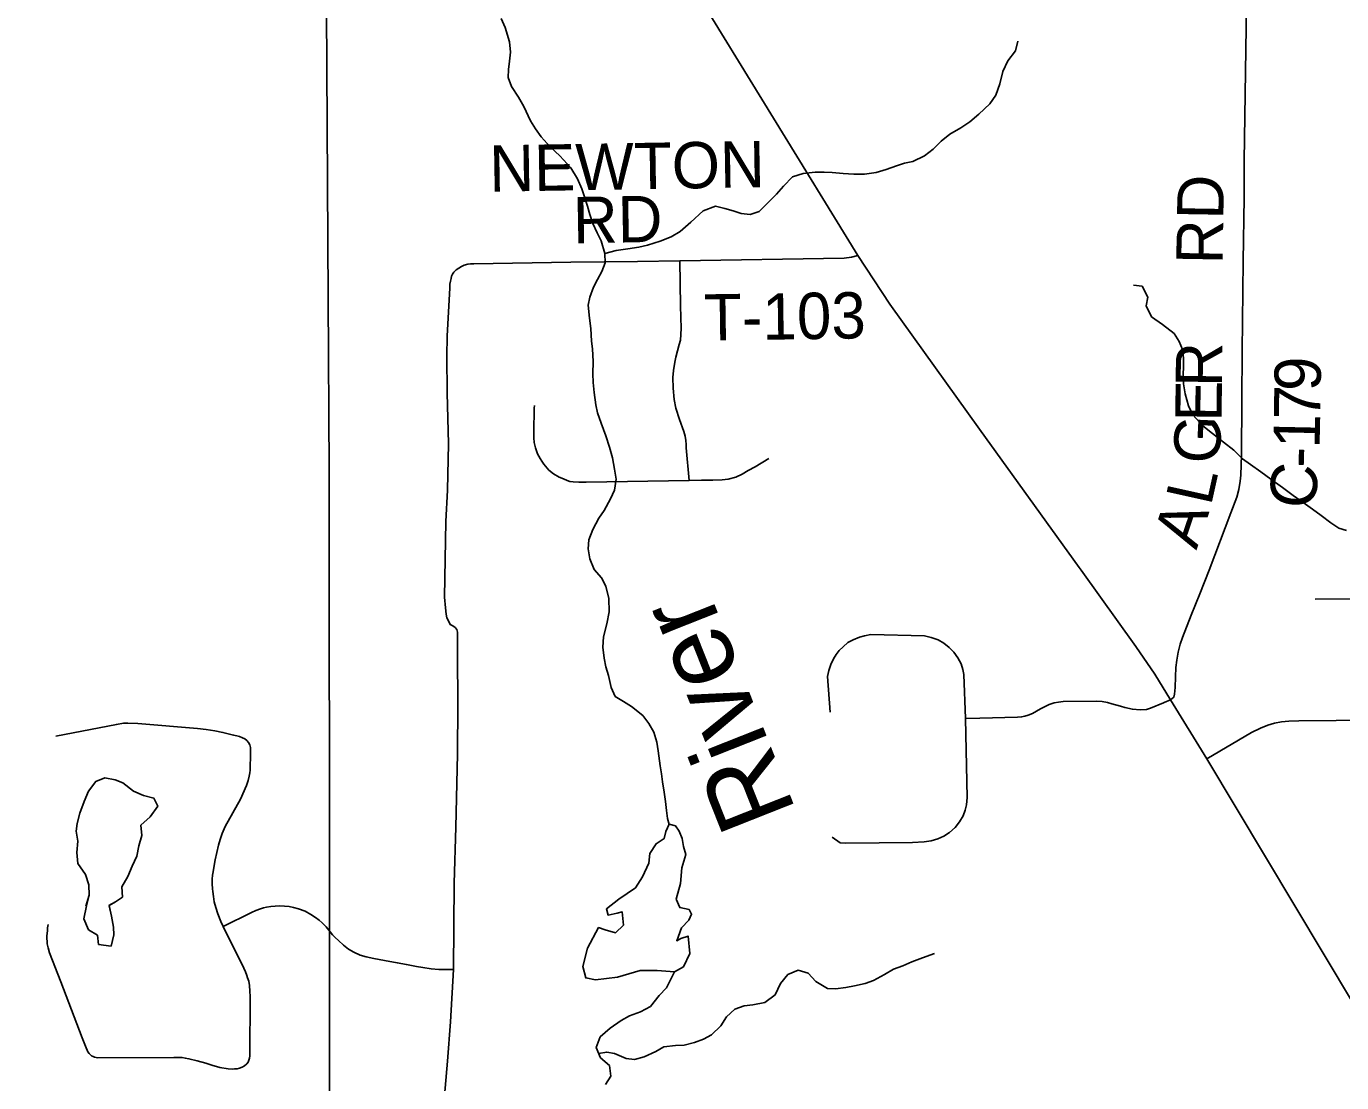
# Model space of a CAD drawing. Extents: x 0 to 34, y 0 to 22.
# Drawn here: x 2.919 to 4.531, y 18.93 to 20.225 of the extents above; entities that cross this region are included whole.
import ezdxf

# ---------------------------------------------------------------- set-up
doc = ezdxf.new("R2010")
doc.units = 0
for name, color, linetype in [('Default', 7, 'Continuous'), ('GM_X_City_Street', 7, 'Continuous'), ('GM_X_County_Road', 7, 'Continuous'), ('GM_X_County_Road_Text', 7, 'Continuous'), ('GM_X_Minor_Lake', 7, 'Continuous'), ('GM_X_Minor_River', 7, 'Continuous'), ('GM_X_Minor_River_Text', 7, 'Continuous'), ('GM_X_State_Route', 7, 'Continuous'), ('GM_X_Township_Road', 7, 'Continuous'), ('GM_X_Township_Road_Text', 7, 'Continuous'), ('SH_Cut_Line', 7, 'Continuous')]:
    doc.layers.add(name, color=color, linetype=linetype)

msp = doc.modelspace()

# ---------------------------------------------------------------- linework, layer by layer
at = {"layer": 'Default'}
msp.add_lwpolyline([(3.2826, 20.9), (2.1, 20.9), (2.1, 15.8248), (3.2829, 15.8433), (3.2832, 16.3898), (3.2835, 17.0107), (3.2837, 17.3796), (3.2907, 18.4315), (3.2904, 19.1173), (3.2901, 19.68), (3.2888, 19.8918), (3.2845, 20.5998), (3.2843, 20.6124)], close=True, dxfattribs=at)
msp.add_lwpolyline([(8.1749, 20.9), (3.2826, 20.9), (3.2843, 20.6124), (3.2845, 20.5998), (3.2888, 19.8918), (3.2901, 19.68), (3.2904, 19.1173), (3.2907, 18.4315), (3.2837, 17.3796), (3.2835, 17.0107), (3.2832, 16.3898), (3.2829, 15.8433), (3.425, 15.8449), (3.4609, 15.8448), (3.6703, 15.8472), (4.3446, 15.8524), (4.6273, 15.8569)], dxfattribs=at)
at = {"layer": 'GM_X_City_Street'}
for points in [[(4.3214, 19.3994), (4.3252, 19.4025), (4.3261, 19.4061), (4.3269, 19.4144), (4.3276, 19.4277), (4.3279, 19.4388), (4.329, 19.4479), (4.3308, 19.4577), (4.3332, 19.4676), (4.3361, 19.4757), (4.3468, 19.5031), (4.3573, 19.5295), (4.3685, 19.5583)], [(4.4986, 19.5226), (4.6144, 19.5236), (4.6796, 19.5238)], [(4.3659, 19.327), (4.4205, 19.3591), (4.4317, 19.3646), (4.4405, 19.3681), (4.4488, 19.3706), (4.4575, 19.3722), (4.4663, 19.3731), (4.4785, 19.3736), (4.6158, 19.3747)]]:
    msp.add_lwpolyline(points, dxfattribs=at)
at = {"layer": 'GM_X_County_Road'}
for points in [[(4.4118, 20.0552), (4.4118, 20.0602), (4.4144, 20.2509), (4.4155, 20.3706)], [(4.4116, 20.0148), (4.4117, 20.0189), (4.4118, 20.0552)], [(4.3685, 19.5583), (4.3953, 19.6286), (4.4026, 19.6479), (4.405, 19.6573), (4.4067, 19.6676), (4.4076, 19.6747), (4.4084, 19.6997), (4.4089, 19.7665), (4.4093, 19.8269), (4.4104, 19.9371), (4.4116, 20.0148)]]:
    msp.add_lwpolyline(points, dxfattribs=at)
at = {"layer": 'GM_X_Minor_Lake'}
for points in [[(3.0371, 19.2974), (3.0276, 19.3011), (3.015, 19.3036), (3.0037, 19.2992), (2.9951, 19.2873), (2.9896, 19.2747), (2.9841, 19.2605), (2.9809, 19.2479), (2.9799, 19.2384), (2.982, 19.2259), (2.9807, 19.2122), (2.9817, 19.1985), (2.9914, 19.185), (2.9954, 19.1725), (2.9957, 19.1599), (2.9923, 19.1466)], [(3.0371, 19.2974), (3.0276, 19.3011), (3.015, 19.3036), (3.0037, 19.2992), (2.9951, 19.2873), (2.9896, 19.2747), (2.9841, 19.2605), (2.9809, 19.2479), (2.9799, 19.2384), (2.982, 19.2259), (2.9807, 19.2122), (2.9817, 19.1985), (2.9914, 19.185), (2.9954, 19.1725), (2.9957, 19.1599), (2.9917, 19.1464)], [(3.0198, 19.147), (3.028, 19.1516), (3.0367, 19.1574), (3.0356, 19.1701), (3.043, 19.1827), (3.0485, 19.1954), (3.054, 19.2076), (3.0565, 19.2202), (3.0601, 19.2332), (3.0591, 19.2457), (3.0704, 19.2557), (3.0797, 19.2688), (3.075, 19.2786), (3.0624, 19.2819), (3.0502, 19.2874), (3.0371, 19.2974)], [(3.0201, 19.1472), (3.028, 19.1516), (3.0367, 19.1574), (3.0356, 19.1701), (3.043, 19.1827), (3.0485, 19.1954), (3.054, 19.2076), (3.0565, 19.2202), (3.0601, 19.2332), (3.0591, 19.2457), (3.0704, 19.2557), (3.0797, 19.2688), (3.075, 19.2786), (3.0624, 19.2819), (3.0502, 19.2874), (3.0371, 19.2974)], [(3.7153, 19.1551), (3.7207, 19.1741), (3.7224, 19.1935), (3.7272, 19.2098), (3.7245, 19.2197), (3.7225, 19.2292), (3.719, 19.2382), (3.7144, 19.245), (3.7068, 19.2469), (3.7027, 19.2381), (3.7005, 19.2293), (3.6907, 19.2228), (3.6829, 19.211), (3.6818, 19.1992), (3.674, 19.1824), (3.6654, 19.169), (3.6449, 19.1549)], [(2.9923, 19.1466), (2.989, 19.1308), (2.9951, 19.1175), (3.0061, 19.1106), (3.0071, 19.0993)], [(3.0071, 19.0992), (3.0061, 19.1106), (2.9951, 19.1175), (2.989, 19.1308), (2.9923, 19.1466)], [(3.0071, 19.0993), (3.0225, 19.0974), (3.0259, 19.111), (3.0255, 19.1206), (3.0232, 19.1339), (3.0201, 19.1472)], [(3.0201, 19.1468), (3.0232, 19.1339), (3.0255, 19.1206), (3.0259, 19.111), (3.0225, 19.0974), (3.0072, 19.0993)], [(3.6449, 19.1549), (3.6298, 19.143), (3.6318, 19.1354), (3.6428, 19.1378), (3.6492, 19.1394), (3.6509, 19.1231), (3.6411, 19.1138), (3.6282, 19.1175), (3.6202, 19.1201), (3.6067, 19.0949), (3.6009, 19.0724), (3.6044, 19.0584), (3.6166, 19.0562), (3.6435, 19.0591), (3.6711, 19.0674), (3.692, 19.0676), (3.7133, 19.0659), (3.7242, 19.0721), (3.732, 19.0885), (3.7299, 19.1097), (3.7209, 19.1066), (3.716, 19.1039), (3.7219, 19.1199), (3.7309, 19.1291), (3.7343, 19.1364), (3.7312, 19.1421), (3.7198, 19.1446), (3.7153, 19.1551)]]:
    msp.add_lwpolyline(points, dxfattribs=at)
at = {"layer": 'GM_X_Minor_River'}
for points in [[(3.5009, 20.2346), (3.5055, 20.2236), (3.511, 20.2062), (3.5122, 20.1933), (3.5108, 20.1823), (3.5097, 20.172), (3.5094, 20.1625), (3.5133, 20.1512), (3.5221, 20.1383), (3.5287, 20.127), (3.5368, 20.1092), (3.5429, 20.0994), (3.5498, 20.0896), (3.5609, 20.0775), (3.5727, 20.0662), (3.5861, 20.0516), (3.5942, 20.0383), (3.5996, 20.0258), (3.6031, 20.016), (3.6066, 20.0046), (3.6093, 19.9944), (3.6132, 19.9834), (3.6186, 19.9721), (3.6232, 19.9623), (3.6279, 19.9467), (3.6284, 19.935), (3.6243, 19.9247), (3.6187, 19.9148), (3.6138, 19.9052), (3.6094, 19.893), (3.6076, 19.8832), (3.6089, 19.8672), (3.6105, 19.8547), (3.6117, 19.8391), (3.6126, 19.8297), (3.6135, 19.8141), (3.6132, 19.7989), (3.6137, 19.7883), (3.6149, 19.7761), (3.6169, 19.761), (3.6189, 19.7511), (3.6232, 19.7386), (3.629, 19.7231), (3.6337, 19.7091), (3.6372, 19.6962), (3.6399, 19.6822), (3.6416, 19.6697), (3.6398, 19.6564), (3.6349, 19.6457), (3.6271, 19.6316), (3.6207, 19.622), (3.6133, 19.6083), (3.6081, 19.5957), (3.6074, 19.5843), (3.6094, 19.5722), (3.6148, 19.5593), (3.6236, 19.5488)], [(3.6279, 19.9467), (3.6419, 19.9503), (3.6559, 19.9523), (3.6695, 19.9543), (3.6801, 19.9567), (3.6955, 19.9617), (3.7091, 19.9672), (3.7204, 19.9734), (3.7332, 19.9849), (3.7486, 19.999), (3.7637, 20.0045), (3.7751, 20.0019), (3.785, 19.999), (3.7949, 19.9956), (3.8059, 19.9946), (3.8172, 19.9981), (3.8277, 20.0088), (3.8382, 20.0192), (3.8469, 20.0291), (3.8581, 20.0406), (3.871, 20.0445), (3.8857, 20.0462), (3.8967, 20.0463), (3.9066, 20.046), (3.9202, 20.0446), (3.9331, 20.0439), (3.9463, 20.044), (3.9603, 20.0461), (3.9728, 20.0496), (3.9853, 20.0542), (3.9951, 20.0574), (4.0053, 20.0593), (4.0196, 20.0663), (4.0305, 20.0744), (4.0403, 20.0843), (4.0508, 20.0928), (4.0644, 20.1005), (4.0753, 20.1082), (4.0862, 20.1174), (4.0998, 20.13), (4.1072, 20.1407), (4.112, 20.1548), (4.1157, 20.1697), (4.122, 20.183), (4.1314, 20.1952), (4.1343, 20.207)], [(4.2758, 19.9079), (4.2864, 19.9065), (4.2934, 19.8929), (4.2916, 19.8826), (4.2981, 19.869), (4.3115, 19.8596), (4.3256, 19.8487), (4.3321, 19.8389), (4.3359, 19.8287), (4.3372, 19.8181), (4.3373, 19.8078), (4.337, 19.7983), (4.3374, 19.7869), (4.3391, 19.7744), (4.3433, 19.76), (4.3487, 19.7487), (4.361, 19.7351), (4.3728, 19.7257), (4.3861, 19.7152), (4.3991, 19.7054), (4.4094, 19.6949), (4.4193, 19.6878), (4.4319, 19.6788), (4.4445, 19.6701), (4.4586, 19.6596), (4.4715, 19.6499), (4.4841, 19.6412), (4.4955, 19.633), (4.5058, 19.6255), (4.518, 19.6165), (4.5275, 19.6097), (4.537, 19.6068)], [(3.6236, 19.5488), (3.629, 19.5389), (3.6329, 19.5234), (3.6331, 19.5071), (3.6302, 19.4926), (3.6261, 19.4766), (3.6255, 19.4641), (3.6271, 19.4505), (3.6291, 19.4398), (3.6322, 19.4292), (3.6357, 19.4145), (3.6404, 19.4035), (3.6507, 19.3971), (3.6605, 19.3911), (3.6743, 19.3802), (3.6816, 19.3704), (3.6881, 19.3595), (3.6916, 19.3474), (3.6932, 19.3367), (3.6956, 19.3185), (3.6972, 19.3087), (3.6984, 19.2988), (3.7008, 19.2863), (3.7024, 19.2745), (3.7033, 19.2635), (3.7045, 19.2537), (3.7066, 19.2465)], [(3.6203, 18.9657), (3.6303, 18.9674), (3.6398, 18.9656), (3.6539, 18.9597), (3.6641, 18.9583), (3.6762, 18.9618), (3.6902, 18.968), (3.7, 18.9738), (3.7145, 18.9755), (3.7251, 18.9759), (3.7376, 18.9791), (3.7489, 18.9834), (3.7587, 18.9884), (3.77, 18.9995), (3.7771, 19.0106), (3.7873, 19.0202), (3.7986, 19.0241), (3.8093, 19.0254), (3.824, 19.0282), (3.8368, 19.0378), (3.8432, 19.0515), (3.8522, 19.0626), (3.865, 19.0677), (3.8772, 19.0644), (3.8864, 19.0538), (3.9009, 19.0452), (3.9108, 19.045), (3.9233, 19.0466), (3.9339, 19.0486), (3.9468, 19.0514), (3.9574, 19.0553), (3.9706, 19.0626), (3.9819, 19.0692), (3.9933, 19.0731), (4.0042, 19.0781), (4.0171, 19.0832), (4.0318, 19.0883)], [(3.7133, 19.0659), (3.7036, 19.0464), (3.6945, 19.0368), (3.684, 19.0234), (3.6716, 19.0169), (3.6583, 19.0118), (3.6478, 19.006), (3.6342, 18.9967), (3.6221, 18.986), (3.6173, 18.973), (3.6224, 18.9605), (3.6335, 18.9508), (3.6351, 18.9379), (3.6287, 18.9275)]]:
    msp.add_lwpolyline(points, dxfattribs=at)
at = {"layer": 'GM_X_State_Route'}
for points in [[(4.2093, 19.5616), (4.0871, 19.7314), (3.9772, 19.8843), (3.938, 19.944), (3.7312, 20.2812), (3.6198, 20.4626), (3.5672, 20.5512), (3.4765, 20.7041)], [(4.3214, 19.3994), (4.302, 19.4307), (4.279, 19.4649), (4.2116, 19.5584), (4.2093, 19.5616)], [(4.6215, 18.9), (4.5951, 18.9439), (4.5458, 19.0264), (4.3659, 19.327), (4.3214, 19.3994)]]:
    msp.add_lwpolyline(points, dxfattribs=at)
at = {"layer": 'GM_X_Township_Road'}
for points in [[(3.4427, 19.9239), (3.4458, 19.9265), (3.449, 19.9286), (3.4521, 19.9308), (3.4556, 19.9324), (3.4598, 19.9335), (3.4631, 19.9339), (3.4674, 19.934), (3.5862, 19.9358), (3.6681, 19.9368)], [(3.6681, 19.9368), (3.7199, 19.9374), (3.9213, 19.941), (3.9302, 19.9421), (3.938, 19.944)], [(3.7312, 19.6684), (3.7277, 19.7085), (3.7277, 19.7126), (3.7273, 19.7172), (3.7262, 19.7226), (3.7248, 19.7282), (3.7192, 19.743), (3.7149, 19.7571), (3.713, 19.7676), (3.7118, 19.7815), (3.7114, 19.7944), (3.7121, 19.8031), (3.7137, 19.8133), (3.7148, 19.8196), (3.717, 19.8271), (3.7191, 19.8349), (3.7205, 19.8402), (3.7215, 19.8546), (3.7205, 19.8825), (3.7199, 19.9374)], [(3.4472, 19.4741), (3.4474, 19.477), (3.4474, 19.4823), (3.4463, 19.4854), (3.4444, 19.488), (3.4417, 19.49), (3.4384, 19.4917), (3.4358, 19.4969), (3.4343, 19.4999), (3.4332, 19.5045), (3.4324, 19.512), (3.4313, 19.5252), (3.4331, 19.6179), (3.4351, 19.6564), (3.4364, 19.7134), (3.4345, 19.7759), (3.4343, 19.8209), (3.4344, 19.8454), (3.4378, 19.9046), (3.438, 19.909), (3.4386, 19.9125), (3.4393, 19.916), (3.4401, 19.9186), (3.441, 19.9211), (3.4427, 19.9239)], [(3.5415, 19.7603), (3.5414, 19.7568), (3.5411, 19.7476), (3.5409, 19.7371), (3.5409, 19.7288), (3.5409, 19.7207), (3.5414, 19.7148), (3.5428, 19.7083), (3.5454, 19.7011), (3.5487, 19.6954), (3.5508, 19.6919), (3.5532, 19.6881), (3.5594, 19.6808), (3.5651, 19.6763), (3.5719, 19.6722), (3.577, 19.6703), (3.5816, 19.6682), (3.5851, 19.6671), (3.5891, 19.6666), (3.5959, 19.6663), (3.605, 19.6663), (3.7312, 19.6684), (3.7464, 19.6685), (3.7604, 19.6688), (3.7716, 19.669), (3.779, 19.67), (3.7886, 19.6723), (3.7962, 19.676), (3.8034, 19.6805), (3.8123, 19.6852), (3.829, 19.6954)], [(4.07, 19.3766), (4.0678, 19.4305), (4.0666, 19.4367), (4.0645, 19.4436), (4.0606, 19.451), (4.0558, 19.4577), (4.05, 19.4637), (4.0436, 19.4687), (4.0364, 19.4729), (4.0281, 19.4759), (4.0198, 19.4777), (3.954, 19.4793), (3.9461, 19.4779), (3.9399, 19.4761), (3.9323, 19.4729), (3.9259, 19.4696), (3.9199, 19.4644), (3.9153, 19.46), (3.9116, 19.4551), (3.9081, 19.4498), (3.9049, 19.4427), (3.9026, 19.4353), (3.901, 19.428), (3.9042, 19.3842)], [(3.4284, 18.8808), (3.435, 18.9564), (3.4386, 19.0044), (3.4423, 19.0685), (3.4432, 19.1745), (3.4453, 19.2432), (3.4472, 19.3327), (3.4477, 19.3937), (3.4472, 19.4554), (3.4471, 19.4702), (3.4472, 19.4741)], [(4.3126, 19.3956), (4.3136, 19.3959), (4.3214, 19.3994)], [(4.07, 19.3766), (4.0876, 19.3769), (4.1336, 19.3779), (4.1387, 19.3784), (4.1428, 19.3794), (4.1469, 19.3805), (4.1522, 19.3827), (4.1571, 19.3855), (4.162, 19.3884), (4.1675, 19.3913), (4.1726, 19.3936), (4.1785, 19.3956), (4.184, 19.3964), (4.1899, 19.3972), (4.231, 19.3978), (4.2374, 19.3971), (4.244, 19.3959), (4.2495, 19.3944), (4.26, 19.3915), (4.2654, 19.3898), (4.2747, 19.3877), (4.284, 19.3869), (4.2917, 19.3873), (4.2966, 19.389), (4.3126, 19.3956)], [(2.9549, 19.3548), (3.0291, 19.3691), (3.038, 19.3706), (3.0431, 19.3709), (3.0555, 19.3703), (3.1285, 19.3642), (3.1392, 19.3631), (3.1497, 19.3614), (3.1597, 19.3594), (3.1727, 19.3562), (3.1766, 19.3552), (3.1802, 19.3543), (3.1838, 19.3529), (3.1866, 19.3514), (3.1892, 19.3494)], [(3.9065, 19.231), (3.9164, 19.2241), (3.9231, 19.2234), (4.0049, 19.2245), (4.0192, 19.2252), (4.0279, 19.2264), (4.0362, 19.2289), (4.0436, 19.2321), (4.0505, 19.2365), (4.0572, 19.243), (4.0627, 19.2499), (4.0671, 19.2572), (4.0696, 19.2639), (4.0714, 19.2708), (4.0719, 19.2796), (4.07, 19.3766)], [(3.1888, 18.9531), (3.1905, 18.9552), (3.1916, 18.9574), (3.1924, 18.9601), (3.1928, 18.9627), (3.1931, 19.0355), (3.1928, 19.0423), (3.1923, 19.0489), (3.1914, 19.0542), (3.19, 19.0584), (3.189, 19.0614), (3.1873, 19.066), (3.1855, 19.0705), (3.1599, 19.1216), (3.1571, 19.1277), (3.1534, 19.1371), (3.1509, 19.1449), (3.1491, 19.1517), (3.148, 19.158), (3.1472, 19.1642), (3.1468, 19.1676), (3.1466, 19.1739), (3.1465, 19.1796), (3.147, 19.1844), (3.1476, 19.1884), (3.1489, 19.1964), (3.1502, 19.2031), (3.1544, 19.221), (3.1562, 19.2279), (3.1587, 19.2355), (3.1626, 19.2439), (3.1812, 19.2775), (3.1887, 19.2941), (3.1907, 19.3003), (3.1919, 19.3057), (3.1928, 19.31), (3.193, 19.3133), (3.1935, 19.3344), (3.1933, 19.3409), (3.1925, 19.3441), (3.191, 19.3472), (3.1892, 19.3494)], [(3.1599, 19.1216), (3.1948, 19.1385), (3.2002, 19.1409), (3.2057, 19.1431), (3.2093, 19.1442), (3.2132, 19.1452), (3.2185, 19.1461), (3.2239, 19.1465), (3.2294, 19.1466), (3.2353, 19.1463), (3.2407, 19.1458), (3.2461, 19.1448), (3.2524, 19.1431), (3.2604, 19.1401), (3.2675, 19.1363), (3.2732, 19.1326), (3.2775, 19.1292), (3.2812, 19.1259), (3.2861, 19.1209), (3.2913, 19.1147), (3.2942, 19.1114), (3.2974, 19.1078)], [(2.9455, 19.124), (2.9448, 19.1197), (2.9445, 19.1166), (2.944, 19.1096), (2.9443, 19.1001), (2.9453, 19.0953), (2.9473, 19.0892), (2.9611, 19.0536), (2.987, 18.9848), (2.9911, 18.9746), (2.9942, 18.9679), (2.9957, 18.9657), (2.9973, 18.964), (2.9987, 18.963), (3.0008, 18.9619), (3.0024, 18.9611), (3.0045, 18.9606), (3.0065, 18.9605), (3.0997, 18.961), (3.1053, 18.9609), (3.1098, 18.9606), (3.1135, 18.9601), (3.118, 18.9593), (3.128, 18.9568), (3.1386, 18.9537), (3.146, 18.9515), (3.1559, 18.9487), (3.1661, 18.9471), (3.1717, 18.9466), (3.1739, 18.9467), (3.1773, 18.947), (3.1799, 18.9479), (3.1832, 18.9491), (3.186, 18.9506), (3.1888, 18.9531)], [(3.2974, 19.1078), (3.3012, 19.1043), (3.3074, 19.0987), (3.3138, 19.0936), (3.3203, 19.0901), (3.3279, 19.0864), (3.3351, 19.0843), (3.3445, 19.0822), (3.3577, 19.0798), (3.3734, 19.0769), (3.3847, 19.0747), (3.3971, 19.0723), (3.4047, 19.0711), (3.4151, 19.0696), (3.4243, 19.0688), (3.4423, 19.0685)]]:
    msp.add_lwpolyline(points, dxfattribs=at)
at = {"layer": 'SH_Cut_Line'}
for points in [[(3.2826, 20.9), (2.1, 20.9), (2.1, 14.1), (3.2807, 14.1), (3.2808, 14.1155), (3.2822, 14.2781), (3.2841, 14.501), (3.2832, 14.8896), (3.2811, 15.7294), (3.2815, 15.7537), (3.2829, 15.8433), (3.2832, 16.3898), (3.2835, 17.0107), (3.2837, 17.3796), (3.2907, 18.4315), (3.2904, 19.1173), (3.2901, 19.68), (3.2888, 19.8918), (3.2845, 20.5998), (3.2843, 20.6124)], [(3.2807, 14.1), (8.9, 14.1), (8.9, 20.9), (3.2826, 20.9), (3.2843, 20.6124), (3.2845, 20.5998), (3.2888, 19.8918), (3.2901, 19.68), (3.2904, 19.1173), (3.2907, 18.4315), (3.2837, 17.3796), (3.2835, 17.0107), (3.2832, 16.3898), (3.2829, 15.8433), (3.2815, 15.7537), (3.2811, 15.7294), (3.2832, 14.8896), (3.2841, 14.501), (3.2822, 14.2781), (3.2808, 14.1155)]]:
    msp.add_lwpolyline(points, close=True, dxfattribs=at)

# ---------------------------------------------------------------- texts
at = {"layer": 'GM_X_County_Road_Text'}
for s, height, rotation, p in [('RD', 0.05682, 89.0341, (4.3851, 19.933)), ('R', 0.0568, 89.196, (4.3843, 19.7826)), ('9', 0.0568, 89.0875, (4.5053, 19.7775)), ('E', 0.0568, 89.2251, (4.3838, 19.7401)), ('7', 0.0568, 89.0341, (4.5047, 19.7425)), ('G', 0.0568, 87.3579, (4.3814, 19.6881)), ('1', 0.0568, 88.778, (4.504, 19.7072)), ('-', 0.0568, 88.3575, (4.5033, 19.6834)), ('L', 0.0568, 77.4666, (4.3708, 19.636)), ('C', 0.0568, 83.4956, (4.4976, 19.6318)), ('A', 0.0568, 71.345, (4.353, 19.5823))]:
    msp.add_text(s, height=height, rotation=rotation, dxfattribs=at).set_placement(p)
at = {"layer": 'GM_X_Minor_River_Text'}
msp.add_text('River', height=0.09475, rotation=111.6022, dxfattribs=at).set_placement((3.8629, 19.2625))
at = {"layer": 'GM_X_Township_Road_Text'}
for s, rotation, p in [('NEWTON', 0.9524, (3.4867, 20.0223)), ('RD', 0.9901, (3.5892, 19.959)), ('T-103', 0.8421, (3.7497, 19.8397))]:
    msp.add_text(s, height=0.05682, rotation=rotation, dxfattribs=at).set_placement(p)

doc.saveas('drawing.dxf')
